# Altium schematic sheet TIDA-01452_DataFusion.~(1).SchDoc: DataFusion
size 431 x 279 mm; Date: Not shown in title block; ApprovedBy: Not shown in title block; CheckedBy: Not shown in title block; Author: Not shown in title block; CompanyName: Not shown in title block; DrawnBy: Il Han Kim; Engineer: Not shown in title block; Organization: Not shown in title block; Address1: Not shown in title block; Address2: Not shown in title block; Address3: Not shown in title block; Address4: Not shown in title block; DocumentNumber: 4; Revision: Use project parameter SCH_Rev; SheetNumber: 5; SheetTotal: 12; PageSetup: Record=PageOptions¦CenterHorizontal=True¦CenterVertical=True¦PrintScale=0.96¦XCorrection=1.00¦YCorrection=1.00¦PrintKind=0¦BorderSize=5000000¦LeftOffset=0¦BottomOffset=0¦Orientation=2¦PaperLength=1000¦PaperWidth=1000¦Scale=100¦PaperSource=15¦PrintQuality=-3¦MediaType=1¦DitherType=10¦PrintScaleMode=1¦PaperKind=A3¦PaperIndex=8
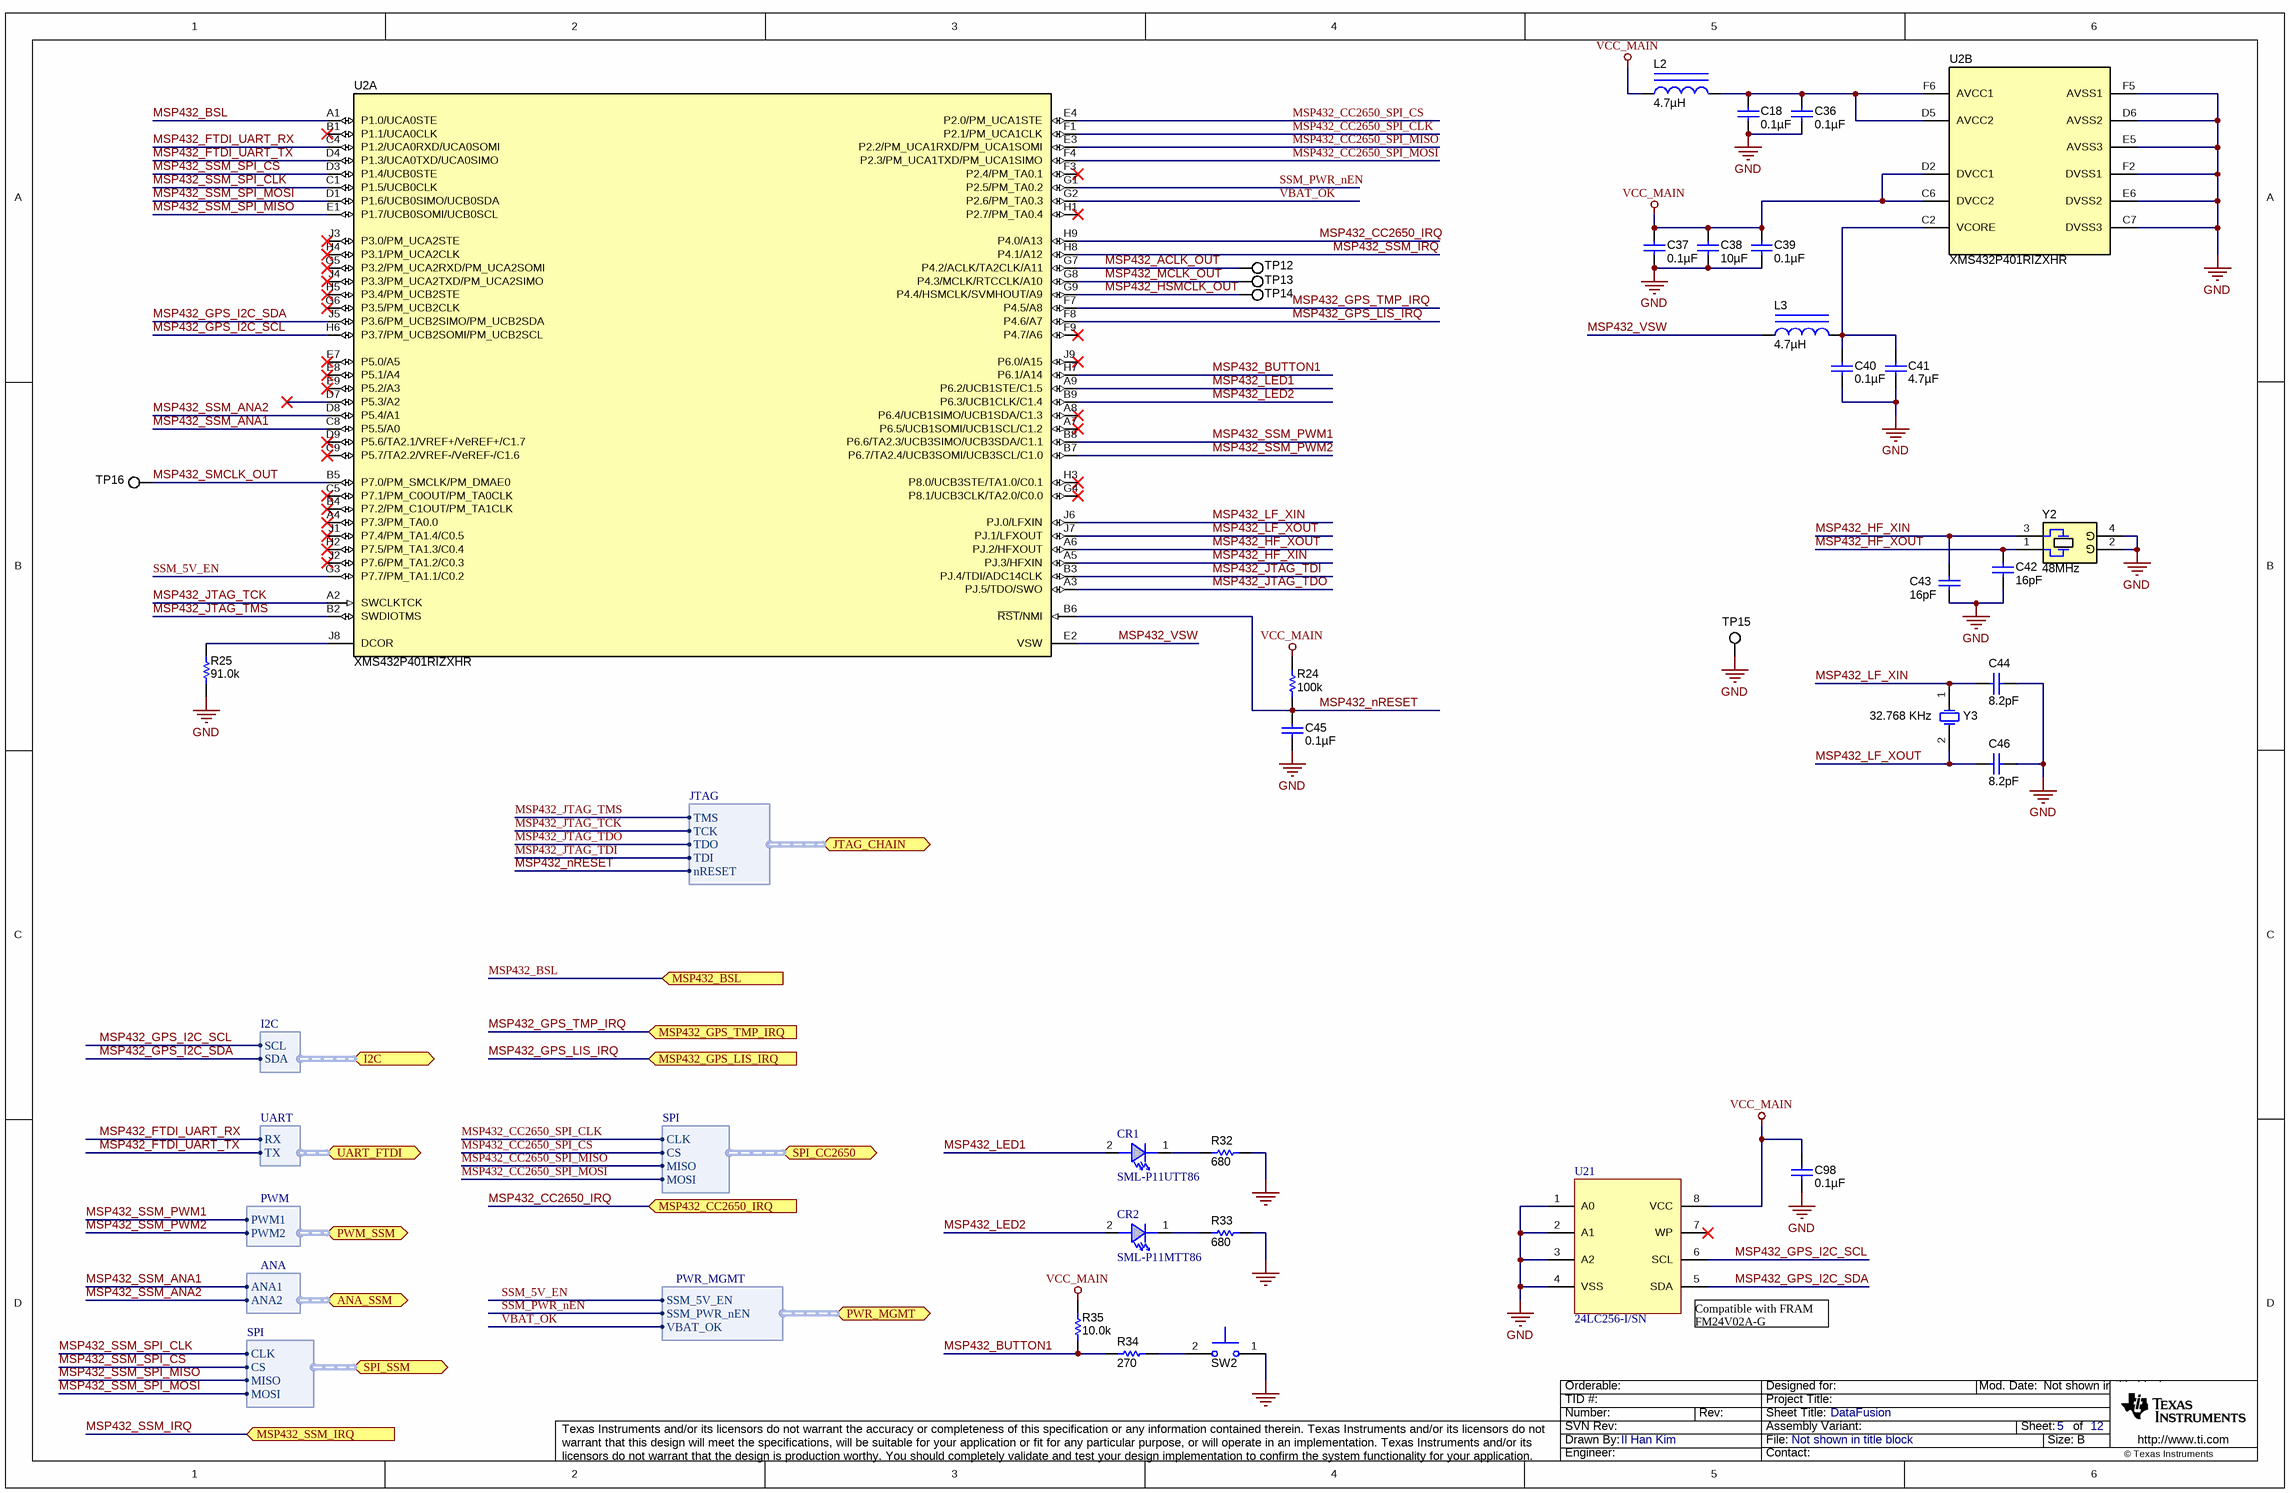
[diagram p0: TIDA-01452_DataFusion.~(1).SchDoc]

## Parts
C18  ValueDisplayed: 0.1µF  [0402]  (hidden comment: GRM155R70J104KA01D)
C36  ValueDisplayed: 0.1µF  [0402]  (hidden comment: GRM155R70J104KA01D)
C37  ValueDisplayed: 0.1µF  [0402]  (hidden comment: GRM155R70J104KA01D)
C38  ValueDisplayed: 10µF  [0603]  (hidden comment: GRM188R60J106ME47D)
C39  ValueDisplayed: 0.1µF  [0402]  (hidden comment: GRM155R70J104KA01D)
C40  ValueDisplayed: 0.1µF  [0402]  (hidden comment: GRM155R70J104KA01D)
C41  ValueDisplayed: 4.7µF  [0402]  (hidden comment: C1005X5R1A475K050BC)
C42  ValueDisplayed: 16pF  [0402]  (hidden comment: GRM1555C1H160JA01D)
C43  ValueDisplayed: 16pF  [0402]  (hidden comment: GRM1555C1H160JA01D)
C44  ValueDisplayed: 8.2pF  [0402]  (hidden comment: GRM1555C1H8R2CA01D)
C45  ValueDisplayed: 0.1µF  [0402]  (hidden comment: GCM155R71H104KE02D)
C46  ValueDisplayed: 8.2pF  [0402]  (hidden comment: GRM1555C1H8R2CA01D)
C98  ValueDisplayed: 0.1µF  [0402]  (hidden comment: GRM155R70J104KA01D)
CR1  SML-P11UTT86  [LEDC1708X67L]
CR2  SML-P11MTT86  [LEDC1707X65L]
L2  ValueDisplayed: 4.7µH  [MLP2520S-S]  (hidden comment: MLP2520S4R7ST0S1)
L3  ValueDisplayed: 4.7µH  [MLP2520S-S]  (hidden comment: MLP2520S4R7ST0S1)
R24  ValueDisplayed: 100k  [0402]  (hidden comment: CRCW0402100KFKED)
R25  ValueDisplayed: 91.0k  [0603]  (hidden comment: RG1608P-913-B-T5)
R32  ValueDisplayed: 680  [0402]  (hidden comment: CRCW0402680RJNED)
R33  ValueDisplayed: 680  [0402]  (hidden comment: CRCW0402680RJNED)
R34  ValueDisplayed: 270  [0402]  (hidden comment: CRCW0402270RFKED)
R35  ValueDisplayed: 10.0k  [0402]  (hidden comment: CRCW040210K0FKED)
SW2  B3U-1000P  [SW_B3U-1000P]  (value not drawn)
TP12  NA  [TPS0.8]  (value not drawn)  (no BOM)
TP13  NA  [TPS0.8]  (value not drawn)  (no BOM)
TP14  NA  [TPS0.8]  (value not drawn)  (no BOM)
TP15  NA  [TPS0.8]  (value not drawn)  (no BOM)
TP16  NA  [TPS0.8]  (value not drawn)  (no BOM)
U2  XMS432P401RIZXHR  [ZXH0080A]  (parts A,B of 2)
U21  24LC256-I/SN  [D0008A_N]
Y2  Frequency: 48MHz  [HEC_X3S048000BG1H-U]  (hidden comment: 732-FA238-48B-K3)
Y3  Frequency: 32.768 KHz  [Epson_FC-135]  (hidden comment: FC-135 32.7680KA-AG0)

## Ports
ANA_SSM (harness ANA), I2C (harness I2C), JTAG_CHAIN (harness JTAG), MSP432_BSL (in), MSP432_CC2650_IRQ (in), MSP432_GPS_LIS_IRQ (in), MSP432_GPS_TMP_IRQ (in), MSP432_SSM_IRQ (in), PWM_SSM (harness PWM), PWR_MGMT (harness PWR_MGMT), SPI_CC2650 (harness SPI), SPI_SSM (harness SPI), UART_FTDI (harness UART)

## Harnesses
UART: RX, TX
SPI: CLK, CS, MISO, MOSI
PWR_MGMT: SSM_5V_EN, VBAT_OK, SSM_PWR_nEN
PWM: PWM1, PWM2
ANA: ANA1, ANA2
JTAG: TMS, TCK, TDO, TDI, nRESET
I2C: SCL, SDA

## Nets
GND: C18.2 C36.2 C37.2 C38.2 C39.2 C40.2 C41.2 C42.2 C43.2 C44.1 C45.2 C46.1 C98.2 R25.1 R32.1 R33.1 SW2.1 TP15.1 U2.C7(DVSS3) U2.D6(AVSS2) U2.E5(AVSS3) U2.E6(DVSS2) U2.F2(DVSS1) U2.F5(AVSS1) U21.1(A0) U21.2(A1) U21.3(A2) U21.4(VSS) Y2.2(GND) Y2.4(GND)
VCC_MAIN: C37.1 C38.1 C39.1 C98.1 L2.1 R24.1 R35.1 U2.C6(DVCC2) U2.D2(DVCC1) U21.8(VCC)
MSP432_ACLK_OUT: TP12.1 U2.G7(P4.2/ACLK/TA2CLK/A11)
MSP432_BSL: U2.A1(P1.0/UCA0STE) ; port MSP432_BSL
MSP432_BUTTON1: R34.2 R35.2 U2.H7(P6.1/A14)
MSP432_CC2650_IRQ: U2.H9(P4.0/A13) ; port MSP432_CC2650_IRQ
MSP432_CC2650_SPI_CLK: U2.F1(P2.1/PM_UCA1CLK) ; port SPI_CC2650.CLK
MSP432_CC2650_SPI_CS: U2.E4(P2.0/PM_UCA1STE) ; port SPI_CC2650.CS
MSP432_CC2650_SPI_MISO: U2.E3(P2.2/PM_UCA1RXD/PM_UCA1SOMI) ; port SPI_CC2650.MISO
MSP432_CC2650_SPI_MOSI: U2.F4(P2.3/PM_UCA1TXD/PM_UCA1SIMO) ; port SPI_CC2650.MOSI
MSP432_FTDI_UART_RX: U2.C4(P1.2/UCA0RXD/UCA0SOMI) ; port UART_FTDI.RX
MSP432_FTDI_UART_TX: U2.D4(P1.3/UCA0TXD/UCA0SIMO) ; port UART_FTDI.TX
MSP432_GPS_I2C_SCL: U2.H6(P3.7/PM_UCB2SOMI/PM_UCB2SCL) U21.6(SCL) ; port I2C.SCL
MSP432_GPS_I2C_SDA: U2.J5(P3.6/PM_UCB2SIMO/PM_UCB2SDA) U21.5(SDA) ; port I2C.SDA
MSP432_GPS_LIS_IRQ: U2.F8(P4.6/A7) ; port MSP432_GPS_LIS_IRQ
MSP432_GPS_TMP_IRQ: U2.F7(P4.5/A8) ; port MSP432_GPS_TMP_IRQ
MSP432_HF_XIN: C43.1 U2.A5(PJ.3/HFXIN) Y2.3
MSP432_HF_XOUT: C42.1 U2.A6(PJ.2/HFXOUT) Y2.1
MSP432_HSMCLK_OUT: TP14.1 U2.G9(P4.4/HSMCLK/SVMHOUT/A9)
MSP432_JTAG_TCK: U2.A2(SWCLKTCK) ; port JTAG_CHAIN.TCK
MSP432_JTAG_TDI: U2.B3(PJ.4/TDI/ADC14CLK) ; port JTAG_CHAIN.TDI
MSP432_JTAG_TDO: U2.A3(PJ.5/TDO/SWO) ; port JTAG_CHAIN.TDO
MSP432_JTAG_TMS: U2.B2(SWDIOTMS) ; port JTAG_CHAIN.TMS
MSP432_LED1: CR1.2(A) U2.A9(P6.2/UCB1STE/C1.5)
MSP432_LED2: CR2.2(A) U2.B9(P6.3/UCB1CLK/C1.4)
MSP432_LF_XIN: C44.2 U2.J6(PJ.0/LFXIN) Y3.1(OSC1)
MSP432_LF_XOUT: C46.2 U2.J7(PJ.1/LFXOUT) Y3.2(OSC2)
MSP432_MCLK_OUT: TP13.1 U2.G8(P4.3/MCLK/RTCCLK/A10)
MSP432_nRESET: C45.1 R24.2 U2.B6(~{RST}/NMI) ; port JTAG_CHAIN.nRESET
MSP432_SMCLK_OUT: TP16.1 U2.B5(P7.0/PM_SMCLK/PM_DMAE0)
MSP432_SSM_ANA1: U2.C8(P5.5/A0) ; port ANA_SSM.ANA1
MSP432_SSM_ANA2: U2.D8(P5.4/A1) ; port ANA_SSM.ANA2
MSP432_SSM_IRQ: U2.H8(P4.1/A12) ; port MSP432_SSM_IRQ
MSP432_SSM_PWM1: U2.B8(P6.6/TA2.3/UCB3SIMO/UCB3SDA/C1.1) ; port PWM_SSM.PWM1
MSP432_SSM_PWM2: U2.B7(P6.7/TA2.4/UCB3SOMI/UCB3SCL/C1.0) ; port PWM_SSM.PWM2
MSP432_SSM_SPI_CLK: U2.C1(P1.5/UCB0CLK) ; port SPI_SSM.CLK
MSP432_SSM_SPI_CS: U2.D3(P1.4/UCB0STE) ; port SPI_SSM.CS
MSP432_SSM_SPI_MISO: U2.E1(P1.7/UCB0SOMI/UCB0SCL) ; port SPI_SSM.MISO
MSP432_SSM_SPI_MOSI: U2.D1(P1.6/UCB0SIMO/UCB0SDA) ; port SPI_SSM.MOSI
MSP432_VSW: L3.1 U2.E2(VSW)
SSM_5V_EN: U2.G3(P7.7/PM_TA1.1/C0.2) ; port PWR_MGMT.SSM_5V_EN
SSM_PWR_nEN: U2.G1(P2.5/PM_TA0.2) ; port PWR_MGMT.SSM_PWR_nEN
VBAT_OK: U2.G2(P2.6/PM_TA0.3) ; port PWR_MGMT.VBAT_OK
NetC18_1: C18.1 C36.1 L2.2 U2.D5(AVCC2) U2.F6(AVCC1)
NetC40_1: C40.1 C41.1 L3.2 U2.C2(VCORE)
NetCR1_1: CR1.1(C) R32.2
NetCR2_1: CR2.1(C) R33.2
NetR25_2: R25.2 U2.J8(DCOR)
NetR34_1: R34.1 SW2.2

Not connected (* = marked no-connect by the designer): U2 A4(P7.3/PM_TA0.0)* A7(P6.5/UCB1SOMI/UCB1SCL/C1.2)* A8(P6.4/UCB1SIMO/UCB1SDA/C1.3)* B1(P1.1/UCA0CLK)* B4(P7.2/PM_C1OUT/PM_TA1CLK)* C5(P7.1/PM_C0OUT/PM_TA0CLK)* C9(P5.7/TA2.2/VREF-/VeREF-/C1.6)* D7(P5.3/A2)* D9(P5.6/TA2.1/VREF+/VeREF+/C1.7)* E7(P5.0/A5)* E8(P5.1/A4)* E9(P5.2/A3)* F3(P2.4/PM_TA0.1)* F9(P4.7/A6)* G4(P8.1/UCB3CLK/TA2.0/C0.0)* G5(P3.2/PM_UCA2RXD/PM_UCA2SOMI)* G6(P3.5/PM_UCB2CLK)* H1(P2.7/PM_TA0.4)* H2(P7.5/PM_TA1.3/C0.4)* H3(P8.0/UCB3STE/TA1.0/C0.1)* H4(P3.1/PM_UCA2CLK)* H5(P3.4/PM_UCB2STE)* J1(P7.4/PM_TA1.4/C0.5)* J2(P7.6/PM_TA1.2/C0.3)* J3(P3.0/PM_UCA2STE)* J4(P3.3/PM_UCA2TXD/PM_UCA2SIMO)* J9(P6.0/A15)*; U21 7(WP)*

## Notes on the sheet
- (near U21) Compatible with FRAM FM24V02A-G

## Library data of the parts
C18 C36 C37 C39 C40 C98 = GRM155R70J104KA01D: CAP, CERM, 0.1 µF, 6.3 V, +/- 10%, X7R, 0402; Manufacturer: MuRata; Polarized: N; CompType: Capacitor; Value: 0.1uF; U/M: EA; Cap_F: 0.0000001; Tolerance_%: 10; Value1: Unknown; VDC_V: 6.3; Value2: 6.3V; TaMin_C: -55; TaMax_C: 125; SizeArea_mm2: 0.5; SizeAreaWB_mm2: 3; SizeX_mm: 1; SizeZ_mm: 0.6; AEC Category: Q200
C38 = GRM188R60J106ME47D: CAP, CERM, 10 µF, 6.3 V, +/- 20%, X5R, 0603; Manufacturer: MuRata; Polarized: N; CompType: Capacitor; Value: 10uF; U/M: EA; Cap_F: 0.00001; Tolerance_%: 20; ESR_ohm: 0.009; Value1: 0.009 ohm; VDC_V: 6.3; Value2: 6.3V; IRMS_A: 2.74; TaMin_C: -55; TaMax_C: 125; SizeArea_mm2: 1.28; SizeAreaWB_mm2: 4.68; SizeX_mm: 1.6; SizeY_mm: 0.8; SizeZ_mm: 1; AEC Category: Q200
C41 = C1005X5R1A475K050BC: CAP, CERM, 4.7 µF, 10 V, +/- 10%, X5R, 0402; Manufacturer: TDK; Polarized: N; CompType: Capacitor; Value: 4.7uF; U/M: EA; Cap_F: 0.0000047; Tolerance_%: 10; Value1: Unknown; Value2: 10V; TaMin_C: -55; TaMax_C: 85; AEC Category: Q200
C42 C43 = GRM1555C1H160JA01D: CAP, CERM, 16 pF, 50 V, +/- 5%, C0G/NP0, 0402; Manufacturer: MuRata; Polarized: N; CompType: Capacitor; Value: 16pF; U/M: EA; Cap_F: 0.000000000016; Tolerance_%: 5; Value1: Unknown; VDC_V: 50; Value2: 50V; TaMin_C: -55; TaMax_C: 125; SizeArea_mm2: 0.5; SizeAreaWB_mm2: 3; SizeX_mm: 1; SizeZ_mm: 0.6; AEC Category: Q200
C44 C46 = GRM1555C1H8R2CA01D: CAP, CERM, 8.2 pF, 50 V, +/- 5%, C0G/NP0, 0402; Manufacturer: MuRata; Polarized: N; CompType: Capacitor; Value: 8.2pF; U/M: EA; Cap_F: 0.0000000000082; Tolerance_%: 5; Value1: Unknown; VDC_V: 50; Value2: 50V; TaMin_C: -55; TaMax_C: 125; SizeArea_mm2: 0.5; SizeAreaWB_mm2: 3; SizeX_mm: 1; SizeZ_mm: 0.6; AEC Category: Q200
C45 = GCM155R71H104KE02D: CAP, CERM, 0.1 µF, 50 V, +/- 10%, X7R, AEC-Q200 Grade 1, 0402; Manufacturer: MuRata; Polarized: N; CompType: Capacitor; Value: 0.1uF; U/M: EA; Cap_F: 0.0000001; Tolerance_%: 10; Value1: Unknown; VDC_V: 50; Value2: 50V; TaMin_C: -55; TaMax_C: 125; AEC Category: Q200; AEC Qualified: Y; AEC Grade: 1
CR1 = SML-P11UTT86: Red 621nm LED Indication - Discrete 1.8V 0402 (1005 Metric); Manufacturer: Rohm Semiconductor; PCB Package: 0402
CR2 = SML-P11MTT86: Green 569nm LED Indication - Discrete 1.9V 0402 (1005 Metric); Manufacturer: Rohm Semiconductor; PCB Package: 0402
L2 L3 = MLP2520S4R7ST0S1: Inductor, Multilayer, Ferrite, 4.7 µH, 0.3 A, 0.143 ohm, SMD; Manufacturer: TDK; Value: 4.7uH; Ind_H: 4.7E-6; Imax_A: 0.3; Irms: 1.4A @ 40C rise; Isat: 0.3A @ 30% inductance drop; DCR_ohm: 0.143; Value2: 0.3A; AEC Category: Q200
R24 = CRCW0402100KFKED: RES, 100 k, 1%, 0.063 W, 0402; Manufacturer: Vishay-Dale; CompType: Resistor; Value: 100k; Res_ohm: 100000; Tolerance_%: 1; Power_W: 0.063; Value2: 0.063W; VDC_V: 50; TempCo: 100 ppm/C; EIA_Code: E96; U/M: EA; AEC Category: Q200
R25 = RG1608P-913-B-T5: RES, 91.0 k, 0.1%, 0.1 W, 0603; Manufacturer: Susumu Co Ltd; CompType: Resistor; Value: 91.0k; Res_ohm: 91000; Value_Code: 91k0; Tolerance_%: 0.1; Value2: 0.1W; VDC_V: 75; TempCo: 25 ppm/C; SizeArea_mm2: 1.28; SizeX_mm: 1.6; SizeY_mm: 0.8; SizeZ_mm: 1; U/M: EA; AEC Category: Q200
R32 R33 = CRCW0402680RJNED: RES, 680, 5%, 0.063 W, 0402; Manufacturer: Vishay-Dale; Value: 680; CompType: Resistor; Value_Code: 680R; Tolerance_%: 5; Power_W: 0.063; Value2: 0.063W; VDC_V: 50; TempCo: 200 ppm/C; EIA_Code: E24; U/M: EA; AEC Category: Q200
R34 = CRCW0402270RFKED: RES, 270, 1%, 0.0625W, 50V, 0402; Manufacturer: Vishay-Dale; Value: 270
R35 = CRCW040210K0FKED: RES, 10.0 k, 1%, 0.063 W, 0402; Manufacturer: Vishay-Dale; CompType: Resistor; Value: 10.0k; Res_ohm: 10000; Value_Code: 10k0; Tolerance_%: 1; Power_W: 0.063; Value2: 0.063W; VDC_V: 50; TempCo: 100 ppm/C; EIA_Code: E96; U/M: EA; AEC Category: Q200
SW2 = B3U-1000P: SWITCH TACTILE SPST-NO 0.05A 12V; Manufacturer: Omron Electronic Components; SymbolCreator: a0412235; VDC_V: 12; SwitchFunction: Off-Mom; PositionCount: 1; CurrentRating_mA: 50
TP12-TP16 = TEST_POINT_ROUND_1.2: Round Test Point, 1.2mm diam.
U2 = XMS432P401RIZXHR: Mixed-Signal Microcontroller, ZXH0080A; Alternate PartNumber: XMS432P401RIZXHT; Manufacturer: Texas Instruments; SymbolCreator: Altium; SizeArea_mm2: 25; SizeAreaWB_mm2: 49; SizeX_mm: 5; SizeZ_mm: 1; CompType: IC; U/M: EA
U21 = 24LC256-I/SN: 256K I2C CMOS Serial EEPROM; Manufacturer: Microchip
Y2 = 732-FA238-48B-K3: Crystal, 48MHz, 10pF, SMD; Manufacturer: Epson
Y3 = FC-135 32.7680KA-AG0: Crystal, 32.768 KHz, 7 pF, SMD; Manufacturer: Epson; U/M: EA; TaMin_C: -40; TaMax_C: 85; Frequency Tolerance: ±20ppm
